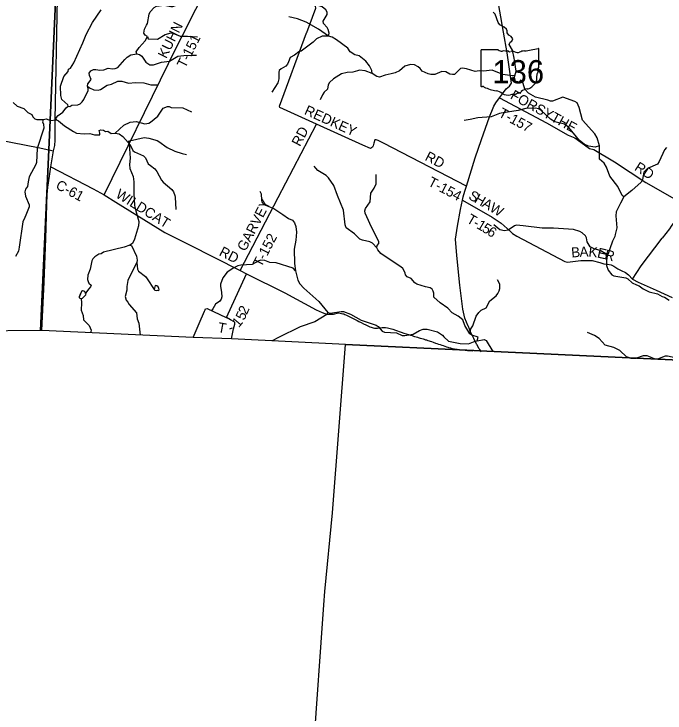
# Model space of a CAD drawing. Extents: x 1525783 to 1900577, y 218250 to 627376.
# Drawn here: x 1625264 to 1644767, y 362753 to 383684 of the extents above; entities that cross this region are included whole.
import ezdxf

# ---------------------------------------------------------------- set-up
doc = ezdxf.new("R2010")
doc.units = 0
for name, color, linetype in [('GM_X_Adjacent_County', 7, 'Continuous'), ('GM_X_County', 7, 'Continuous'), ('GM_X_County_Road', 7, 'Continuous'), ('GM_X_County_Road_Text', 7, 'Continuous'), ('GM_X_Minor_Lake', 7, 'Continuous'), ('GM_X_Minor_River', 7, 'Continuous'), ('GM_X_State_Location', 7, 'Continuous'), ('GM_X_State_Route', 7, 'Continuous'), ('GM_X_State_Shield', 7, 'Continuous'), ('GM_X_Township', 7, 'Continuous'), ('GM_X_Township_Road', 7, 'Continuous'), ('GM_X_Township_Road_Text', 7, 'Continuous'), ('GM_X_Township_ROW', 7, 'Continuous'), ('GM_X_US_Route', 7, 'Continuous')]:
    doc.layers.add(name, color=color, linetype=linetype)

msp = doc.modelspace()

# ---------------------------------------------------------------- linework, layer by layer
at = {"layer": 'GM_X_Adjacent_County'}
for points in [[(1634234, 361625), (1634548, 365997), (1634580, 366395), (1634807, 368748), (1635198, 373791), (1631776, 373952), (1630628, 373995), (1626099, 374208), (1626060, 374210), (1620148, 374148), (1613626, 374093), (1613116, 374096), (1606320, 374160)], [(1634234, 361625), (1634548, 365997), (1634580, 366395), (1634807, 368748), (1635198, 373791), (1639040, 373611), (1639218, 373602), (1647962, 373191)]]:
    msp.add_lwpolyline(points, dxfattribs=at)
at = {"layer": 'GM_X_County'}
msp.add_lwpolyline([(1647962, 373191), (1639218, 373602), (1639040, 373611), (1635198, 373791), (1631776, 373952), (1630628, 373995), (1626099, 374208), (1626060, 374210), (1620148, 374148), (1613626, 374093), (1613116, 374096), (1606320, 374160)], dxfattribs=at)
at = {"layer": 'GM_X_County_Road'}
for points in [[(1617613, 381181), (1618315, 380977), (1620831, 380241), (1621420, 380041), (1622082, 379732), (1622975, 379355), (1623023, 379332), (1623069, 379325), (1623113, 379340), (1623131, 379663), (1623129, 379761), (1623142, 379813), (1623155, 379851), (1623211, 379860), (1623949, 379621), (1624438, 379635), (1624522, 379744), (1624575, 379855), (1624634, 379916), (1624798, 379913), (1625985, 379689), (1626304, 379620), (1626453, 379588)], [(1626373, 379112), (1627634, 378447), (1627962, 378270), (1628319, 378051), (1629159, 377527), (1629779, 377138), (1630498, 376777), (1632043, 376003), (1632225, 375899), (1633377, 375335), (1634321, 374827), (1634498, 374747), (1634576, 374716), (1634632, 374696), (1634686, 374693), (1634832, 374696), (1634985, 374732), (1635076, 374718), (1635114, 374710), (1635143, 374701), (1635178, 374687), (1635230, 374664), (1635305, 374629), (1635368, 374597), (1635428, 374568), (1635487, 374537), (1635548, 374505), (1635598, 374480), (1635664, 374445), (1635735, 374408), (1635801, 374375), (1635867, 374343), (1635927, 374318), (1635967, 374303), (1635995, 374295), (1636026, 374287), (1636064, 374279), (1636107, 374275), (1636151, 374277), (1636222, 374285), (1636289, 374296), (1636351, 374299), (1636396, 374298), (1636455, 374288), (1636531, 374266), (1636611, 374242), (1636688, 374214), (1636748, 374194), (1636800, 374176), (1636866, 374153), (1636939, 374130), (1637015, 374107), (1637079, 374087), (1637143, 374067), (1637190, 374053), (1637229, 374040), (1637267, 374029), (1637313, 374017), (1637349, 374006), (1637372, 374000), (1637400, 373991), (1637430, 373981), (1637479, 373967), (1637518, 373955), (1637556, 373943), (1637591, 373931), (1637592, 373931), (1637601, 373928), (1637611, 373925), (1637617, 373923), (1637657, 373911), (1637697, 373898), (1637735, 373887), (1637775, 373874), (1637821, 373858), (1637895, 373831), (1637933, 373818), (1637984, 373802), (1638027, 373788), (1638077, 373770), (1638122, 373755), (1638172, 373737), (1638222, 373721), (1638257, 373709), (1638281, 373701), (1638341, 373683), (1638394, 373668), (1638458, 373654), (1638529, 373646), (1638558, 373642), (1638591, 373639), (1638656, 373632), (1638708, 373627), (1638851, 373611), (1638877, 373608), (1639005, 373594)]]:
    msp.add_lwpolyline(points, dxfattribs=at)
at = {"layer": 'GM_X_Minor_Lake'}
for points in [[(1629464, 375438), (1629481, 375417), (1629527, 375408), (1629559, 375410), (1629593, 375409), (1629614, 375423), (1629608, 375463), (1629585, 375512), (1629542, 375540), (1629498, 375553)], [(1629498, 375553), (1629464, 375438)], [(1627411, 375325), (1627382, 375362), (1627354, 375388), (1627321, 375395), (1627290, 375371), (1627267, 375322), (1627242, 375278), (1627234, 375256), (1627220, 375228), (1627213, 375210), (1627221, 375190), (1627241, 375174), (1627279, 375161), (1627313, 375177), (1627349, 375204), (1627370, 375224)], [(1627370, 375224), (1627421, 375275), (1627422, 375290), (1627411, 375325)]]:
    msp.add_lwpolyline(points, dxfattribs=at)
at = {"layer": 'GM_X_Minor_River'}
for points in [[(1628941, 382494), (1628921, 382546), (1629010, 382677), (1629193, 382878), (1629266, 383013), (1629194, 383054), (1629155, 383105), (1629173, 383227), (1629239, 383344), (1629266, 383396), (1629315, 383675), (1629346, 383751), (1629461, 383877), (1629533, 383916), (1629760, 383946), (1629964, 383903), (1630020, 383912), (1630135, 383952), (1630380, 384002), (1630450, 384039), (1630526, 384104), (1630844, 384467), (1631024, 384684)], [(1634686, 383020), (1634702, 383114), (1634679, 383220), (1634650, 383277), (1634534, 383397), (1634525, 383467), (1634643, 383667), (1634648, 383737), (1634609, 383812), (1634495, 383894), (1634248, 383978), (1634089, 384069), (1633965, 384165), (1633779, 384406), (1633594, 384534), (1633519, 384573), (1633253, 384683)], [(1626890, 380920), (1626882, 380962), (1626699, 381127), (1626665, 381238), (1626660, 381522), (1626759, 381807), (1626883, 381965), (1626901, 382033), (1626955, 382062), (1627062, 382217), (1627324, 382821), (1627431, 383068), (1627613, 383425), (1627872, 383811)], [(1643531, 378209), (1643479, 378250), (1643356, 378517), (1643109, 378827), (1643015, 379101), (1642941, 379220), (1642805, 379339), (1642800, 379739), (1642736, 379977), (1642662, 380100), (1642296, 380509), (1642193, 380883), (1642139, 381022), (1642069, 381061), (1641701, 381192), (1641395, 381077), (1641331, 381078), (1641253, 381101), (1640882, 381197), (1640680, 381317), (1640570, 381435), (1640519, 381604), (1640494, 381668), (1640430, 381703), (1640413, 381635), (1640359, 381632), (1640289, 381658), (1640259, 381770), (1640264, 381836), (1640309, 381972), (1640256, 382303), (1640245, 382365), (1640193, 382602), (1640094, 382772), (1640123, 382840), (1640176, 382869), (1640207, 382937), (1640162, 383007), (1640091, 383053), (1640034, 383118), (1640033, 383182), (1640016, 383234), (1639951, 383291), (1639818, 383358), (1639765, 383428), (1639677, 383674), (1639622, 383737)], [(1634686, 383020), (1634385, 383233), (1634012, 383435), (1633758, 383534), (1633497, 383600)], [(1629266, 383013), (1629282, 382935), (1629561, 382928), (1629793, 383065), (1629968, 383118), (1630026, 383111), (1630241, 383017), (1630463, 383019), (1630757, 382999)], [(1635997, 381899), (1635988, 381987), (1635912, 382128), (1635803, 382276), (1635605, 382426), (1635473, 382458), (1635339, 382552), (1635267, 382656), (1634923, 382912), (1634800, 382990), (1634686, 383020), (1634498, 383015), (1634330, 382939), (1634226, 382839), (1633867, 382567), (1633797, 382554), (1633669, 382448), (1633542, 382382), (1633486, 382247), (1633456, 382177), (1633411, 382122), (1633270, 382044), (1633207, 381989), (1633194, 381937), (1633195, 381743), (1633167, 381619), (1632984, 381342)], [(1626536, 380511), (1626525, 380575), (1626585, 380641), (1626727, 380746), (1626823, 380877), (1626890, 380920), (1626940, 380917), (1626996, 380952), (1627173, 380961), (1627245, 380994), (1627304, 381055), (1627356, 381122), (1627486, 381391), (1627485, 381457), (1627463, 381527), (1627480, 381597), (1627572, 381718), (1627526, 381843), (1627521, 381911), (1627566, 381982), (1627647, 382023), (1627719, 382024), (1627833, 382004), (1627951, 382016), (1628082, 382066), (1628218, 382041), (1628298, 382048), (1628375, 382079), (1628589, 382322), (1628652, 382387), (1628766, 382457), (1628941, 382494), (1629022, 382471), (1629090, 382423), (1629213, 382241), (1629331, 382163), (1629448, 382163), (1629504, 382182), (1629683, 382237), (1629920, 382273), (1630175, 382425), (1630351, 382439), (1630588, 382455), (1630730, 382446)], [(1640264, 381836), (1640184, 381830), (1639913, 381876), (1639585, 382004), (1639328, 381974), (1639202, 381986), (1639077, 381962), (1638824, 382046), (1638702, 382060), (1638636, 382049), (1638457, 381872), (1638401, 381867), (1638325, 381878), (1638202, 381956), (1638078, 381966), (1637874, 381872), (1637752, 381874), (1637676, 381891), (1637496, 381970), (1637431, 382049), (1637376, 382102), (1637267, 382162), (1637143, 382174), (1636976, 382123), (1636813, 381977), (1636682, 381923), (1636559, 381895), (1636380, 381854), (1636209, 381789), (1636135, 381812), (1635997, 381899), (1635788, 381978), (1635616, 381997), (1635556, 381986), (1635417, 381946), (1635242, 381933), (1635077, 381896), (1634837, 381744), (1634715, 381637), (1634671, 381562), (1634659, 381434), (1634555, 381338), (1634504, 381264), (1634435, 381111)], [(1627463, 381527), (1627528, 381472), (1627661, 381410), (1627787, 381402), (1627855, 381427), (1628058, 381555), (1628182, 381581), (1628380, 381668), (1628496, 381674), (1628693, 381609), (1628900, 381628), (1629150, 381619), (1629365, 381564), (1629556, 381567)], [(1625244, 381037), (1625358, 380927), (1625559, 380850), (1625675, 380736), (1625796, 380672), (1625829, 380605), (1625890, 380542), (1625948, 380523), (1626134, 380528), (1626186, 380531), (1626238, 380540), (1626344, 380496), (1626536, 380511), (1626594, 380486), (1626774, 380339), (1627049, 380166), (1627134, 380115), (1627368, 380095), (1627539, 380106), (1627676, 380070)], [(1628292, 380120), (1628558, 380351), (1628740, 380445), (1628924, 380462), (1629181, 380399), (1629302, 380415), (1629354, 380440), (1629572, 380629), (1629738, 380865), (1629863, 380915), (1629915, 380910), (1629974, 380881), (1630323, 380869), (1630579, 380751)], [(1642800, 379739), (1642671, 379698), (1642479, 379729), (1642342, 379781), (1642202, 379894), (1641884, 380289), (1641752, 380388), (1641468, 380454), (1641340, 380537), (1641046, 380802), (1640972, 380841), (1640883, 380863), (1640600, 380857), (1640369, 380795), (1639863, 380711), (1639807, 380700), (1639559, 380604), (1639156, 380573), (1638925, 380527), (1638748, 380493)], [(1626134, 380528), (1626119, 380458), (1626148, 380383), (1626156, 380269), (1625957, 379658), (1625938, 379241), (1625917, 379174), (1625723, 378808), (1625694, 378658), (1625668, 378517), (1625614, 378441), (1625585, 378360), (1625609, 378233), (1625716, 377971), (1625715, 377913), (1625615, 377658), (1625586, 377593), (1625532, 377465), (1625423, 376706), (1625398, 376584), (1625306, 376418)], [(1627676, 380070), (1627834, 380069), (1627837, 380119), (1627814, 380190), (1627871, 380213), (1627945, 380201), (1628008, 380170), (1628074, 380179), (1628179, 380101), (1628292, 380120), (1628415, 380091), (1628526, 380014), (1628685, 379839), (1628717, 379788), (1628746, 379371), (1628722, 379177), (1628730, 379057), (1628788, 378934), (1628836, 378817), (1628856, 378662), (1628851, 378294), (1628876, 377961), (1628889, 377897), (1629006, 377472), (1628995, 377340), (1628872, 376939), (1628816, 376816), (1628739, 376757), (1628568, 376700), (1627945, 376550), (1627880, 376501), (1627810, 376488), (1627684, 376410), (1627627, 376351), (1627600, 376290), (1627544, 376040), (1627477, 375863), (1627468, 375731), (1627483, 375677), (1627507, 375624), (1627572, 375565), (1627557, 375511), (1627504, 375454), (1627411, 375325)], [(1628685, 379839), (1628728, 379890), (1629166, 379987), (1629300, 379969), (1629549, 379892), (1629605, 379869), (1629856, 379683), (1630081, 379579), (1630302, 379505), (1630431, 379479)], [(1628717, 379788), (1628733, 379786), (1628821, 379600), (1628873, 379557), (1629143, 379441), (1629208, 379373), (1629285, 379192), (1629350, 379143), (1629481, 379046), (1629544, 378967), (1629683, 378707), (1629736, 378646), (1629991, 378431), (1630044, 378360), (1630086, 378251), (1630093, 378195), (1630117, 377834)], [(1644811, 379686), (1644750, 379613), (1644596, 379265), (1644542, 379182), (1644244, 379059), (1644128, 378948), (1644088, 378723), (1644047, 378645), (1643776, 378399), (1643531, 378209), (1643433, 378015), (1643305, 377762), (1643291, 377642), (1643323, 377285), (1643277, 377076), (1643262, 377024), (1643190, 376885), (1643023, 376395), (1643010, 376283), (1643015, 376151), (1643063, 376014), (1643169, 375876), (1643236, 375843), (1643588, 375785), (1643657, 375758), (1643787, 375629), (1643909, 375575), (1643990, 375540), (1644115, 375450), (1644294, 375368), (1644545, 375300), (1644685, 375222), (1644753, 375201), (1644890, 375114)], [(1639135, 373902), (1639168, 374003), (1638983, 374070), (1638922, 374111), (1638768, 374356), (1638705, 374528), (1638568, 374632), (1638392, 374733), (1638256, 374873), (1638027, 375034), (1637837, 375207), (1637837, 375321), (1637820, 375389), (1637787, 375442), (1637730, 375483), (1637590, 375509), (1637333, 375594), (1637272, 375629), (1637158, 375763), (1637039, 375815), (1636996, 375870), (1636983, 375928), (1636954, 375993), (1636917, 376061), (1636856, 376114), (1636323, 376458), (1636252, 376515), (1636167, 376617), (1636136, 376679), (1636003, 376824), (1635929, 376857), (1635704, 376907), (1635626, 376944), (1635461, 377099), (1635216, 377283), (1635181, 377368), (1635132, 377807), (1634954, 378253), (1634841, 378547), (1634688, 378780), (1634615, 378845), (1634368, 379002), (1634305, 379067), (1634260, 379132)], [(1636136, 376679), (1636148, 376751), (1636197, 376814), (1636192, 376876), (1635973, 377299), (1635832, 377609), (1635784, 377718), (1635777, 377789), (1635794, 377864), (1635937, 378058), (1635954, 378322), (1636055, 378469), (1636113, 378600), (1636117, 378873)], [(1632631, 378375), (1632668, 378299), (1632683, 378110), (1632701, 378040), (1632753, 377981), (1633053, 377856), (1633322, 377683), (1633484, 377564), (1633607, 377506), (1633670, 377435), (1633706, 377322), (1633732, 377151), (1633711, 376907), (1633659, 376644), (1633666, 376217), (1633694, 375998), (1633721, 375912), (1633771, 375717), (1633830, 375606), (1633945, 375476), (1634399, 375071), (1634666, 374749), (1634736, 374725), (1635061, 374780), (1635133, 374773), (1635344, 374691), (1635669, 374518), (1636117, 374370), (1636173, 374331), (1636294, 374189), (1636366, 374156), (1636722, 374132), (1636897, 374059), (1636977, 374053), (1637220, 374099), (1637410, 374210), (1637523, 374243), (1637637, 374251), (1637952, 374163), (1638096, 374063), (1638139, 374012), (1638280, 373892), (1638627, 373820), (1638877, 373812), (1639078, 373884), (1639135, 373902), (1639352, 373938), (1639413, 373911), (1639613, 373573)], [(1643023, 376395), (1642991, 376502), (1642821, 376605), (1642645, 376650), (1642526, 376716), (1642439, 376857), (1642413, 376984), (1642382, 377039), (1642287, 377132), (1642218, 377175), (1642022, 377227), (1641425, 377275), (1641088, 377266), (1640517, 377338), (1640319, 377359), (1640262, 377338), (1640072, 377209), (1639959, 377187), (1639820, 377217), (1639640, 377372)], [(1628739, 376757), (1628785, 376751), (1628938, 376436), (1628958, 376315), (1628941, 376245), (1628792, 375955), (1628671, 375701), (1628642, 375519), (1628644, 375413), (1628599, 375228), (1628629, 375111), (1628676, 375054), (1628713, 374989), (1628937, 374733), (1628958, 374551), (1629008, 374428), (1629049, 374070)], [(1628941, 376245), (1628969, 376045), (1628992, 375988), (1629202, 375828), (1629255, 375753), (1629464, 375438)], [(1633694, 375998), (1633629, 376074), (1633115, 376230), (1632925, 376246), (1632776, 376298), (1632660, 376316), (1632602, 376297), (1632402, 376178), (1632055, 376158), (1631970, 376141), (1631847, 376083), (1631655, 375958), (1631518, 375788), (1631451, 375595), (1631446, 375533), (1631484, 375344), (1631494, 375212), (1631473, 375142), (1631430, 375085), (1631298, 374991), (1631226, 374854), (1631171, 374784)], [(1638922, 374111), (1638953, 374259), (1639012, 374344), (1639109, 374633), (1639193, 374750), (1639262, 374813), (1639404, 374881), (1639515, 375095), (1639708, 375244), (1639761, 375319), (1639801, 375399), (1639818, 375461), (1639818, 375579), (1639793, 375655), (1639748, 375724)], [(1627279, 375161), (1627290, 375039), (1627273, 374815), (1627334, 374658), (1627350, 374529), (1627513, 374352), (1627573, 374213), (1627555, 374140)], [(1634666, 374749), (1634631, 374689), (1634275, 374465), (1633834, 374314), (1633191, 373992), (1633002, 373896)], [(1645234, 373308), (1645171, 373373), (1644837, 373441), (1644769, 373442), (1644542, 373351), (1644467, 373345), (1644285, 373432), (1644229, 373449), (1644107, 373447), (1643881, 373372), (1643749, 373367), (1643616, 373417), (1643409, 373605), (1643329, 373650), (1643236, 373698), (1642975, 373772), (1642796, 373969), (1642653, 374054), (1642449, 374147)]]:
    msp.add_lwpolyline(points, dxfattribs=at)
at = {"layer": 'GM_X_State_Route'}
for points in [[(1638875, 374323), (1638871, 374332), (1638771, 374579), (1638713, 374841), (1638615, 375568), (1638535, 376455), (1638495, 376941), (1638552, 377333), (1638640, 377833), (1638697, 378107), (1638723, 378212), (1638769, 378380), (1638820, 378528), (1639083, 379381), (1639266, 379924), (1639507, 380600), (1639614, 380870), (1639641, 380926), (1639703, 381027), (1639813, 381178), (1639926, 381333), (1640012, 381447), (1640108, 381526), (1640151, 381582), (1640165, 381615), (1640034, 382519), (1639926, 383141), (1639742, 384242)], [(1639204, 373654), (1639163, 373723), (1639135, 373777), (1639130, 373786), (1639082, 373881), (1639039, 373967), (1638997, 374051), (1638953, 374141), (1638906, 374243), (1638875, 374323)], [(1639270, 373570), (1639216, 373634), (1639204, 373654)]]:
    msp.add_lwpolyline(points, dxfattribs=at)
at = {"layer": 'GM_X_State_Shield'}
for p, q in [((1640985, 382081), (1640985, 382634)), ((1639245, 382589), (1639245, 381533)), ((1639772, 382607), (1639262, 382607)), ((1640985, 382081), (1640985, 382081))]:
    msp.add_line(p, q, dxfattribs=at)
for centre, major_axis, start_param, end_param in [((1640365, 384048), (1845, 0), 4.814394, 5.042369), ((1640966, 382636), (19.4, 0), 6.141152, 7.989035), ((1639265, 382591), (20.2, 0), 1.712693, 3.28349), ((1639893, 382730), (196, 0), 4.042523, 4.731795), ((1639958, 382014), (702, 0), 1.404758, 1.657858), ((1640117, 382597), (56.4, 0), 3.836095, 5.185415), ((1640200, 382475), (117, 0), 0.950623, 2.079405), ((1640351, 382642), (141, 0), 4.081561, 5.145723), ((1640601, 382285), (371, 0), 1.699011, 2.107814), ((1640981, 382040), (30, 0), 1.883978, 3.671073), ((1640790, 381970), (180, 0), 5.934695, 6.695948), ((1640964, 382079), (20.7, 0), 5.05454, 6.418171), ((1640469, 381779), (462, 0), 5.101752, 6.440018), ((1641054, 381850), (131, 0), 2.387724, 3.262537), ((1639265, 381530), (20.3, 0), 3.00124, 4.508301), ((1639268, 381638), (155, 0), 4.665946, 4.897461), ((1639300, 381472), (56, 0), 0.519207, 1.627899), ((1640006, 382421), (1333, 0), 4.195997, 4.488961), ((1639609, 381058), (417, 0), 0.823519, 1.323587), ((1640663, 381236), (253, 0), 1.647645, 2.488434), ((1640060, 381466), (265, 0), 4.026481, 4.996735), ((1640213, 381101), (217, 0), 1.495662, 1.94098), ((1640232, 381387), (141, 0), 4.691044, 5.507374), ((1640360, 381285), (39.7, 0), 1.147584, 2.315152), ((1640343, 381430), (149, 0), 4.937069, 5.64225)]:
    msp.add_ellipse(centre, major_axis=major_axis, ratio=0.8, start_param=start_param, end_param=end_param, dxfattribs=at)
at = {"layer": 'GM_X_Township'}
for points in [[(1626547, 384955), (1626304, 379620), (1626060, 374210), (1620148, 374148), (1613626, 374093), (1613116, 374096), (1606320, 374160)], [(1647962, 373191), (1639218, 373602), (1639040, 373611), (1635198, 373791), (1631776, 373952), (1630628, 373995), (1626099, 374208), (1626060, 374210), (1626304, 379620), (1626547, 384955)]]:
    msp.add_lwpolyline(points, dxfattribs=at)
at = {"layer": 'GM_X_Township_Road'}
for points in [[(1629926, 382269), (1629927, 382271), (1631097, 384609), (1631463, 385360), (1632385, 387361), (1632999, 390074)], [(1634032, 383125), (1634305, 383861), (1634298, 383913), (1634273, 383948), (1634300, 383984)], [(1638820, 378528), (1636336, 379820), (1636169, 379899), (1636113, 379920), (1636075, 379913), (1636045, 379811), (1636021, 379736), (1636000, 379696), (1635943, 379653), (1635715, 379758), (1634322, 380389), (1633233, 380883), (1633215, 380926), (1634031, 383123), (1634032, 383125)], [(1639813, 381178), (1641220, 380421), (1641862, 380056), (1642067, 379972), (1642502, 379658), (1642630, 379628), (1643252, 379255), (1644194, 378642), (1645399, 377949)], [(1632043, 376003), (1633182, 378192), (1634322, 380389)], [(1638697, 378107), (1639593, 377600), (1639862, 377423), (1640124, 377181), (1640197, 377115), (1640330, 377032), (1641764, 376274), (1641846, 376255), (1642248, 376299), (1642585, 376304), (1642809, 376246), (1642934, 376201), (1643040, 376193), (1643156, 376175), (1643229, 376129), (1643352, 376049), (1643451, 376003), (1643579, 375948), (1643668, 375878), (1643789, 375741), (1643960, 375650), (1644505, 375418), (1644984, 375198)], [(1645399, 377949), (1644955, 377329), (1644896, 377252), (1644681, 376969)], [(1630628, 373995), (1630815, 374416), (1630974, 374786), (1630989, 374830), (1631006, 374852), (1631048, 374861), (1631620, 374593), (1631632, 374591), (1632225, 375899)], [(1631776, 373952), (1631843, 374253), (1631876, 374399), (1631884, 374450), (1631860, 374462), (1631749, 374527), (1631632, 374591)]]:
    msp.add_lwpolyline(points, dxfattribs=at)
at = {"layer": 'GM_X_Township_ROW'}
for points in [[(1627962, 378270), (1629892, 382201), (1629926, 382269)], [(1643789, 375741), (1644051, 376140), (1644681, 376969)]]:
    msp.add_lwpolyline(points, dxfattribs=at)
at = {"layer": 'GM_X_US_Route'}
msp.add_lwpolyline([(1626099, 374208), (1626164, 375656), (1626214, 376949), (1626248, 377977), (1626259, 378278), (1626283, 378495), (1626333, 378830), (1626373, 379112), (1626453, 379588), (1626487, 379744), (1626498, 379906), (1626496, 380508), (1626573, 384168), (1626596, 384866), (1626614, 385250), (1626694, 386483), (1626716, 386972), (1626737, 387835), (1626755, 388652), (1626761, 389086), (1626765, 389240), (1626769, 389345)], dxfattribs=at)

# ---------------------------------------------------------------- texts
at = {"layer": 'GM_X_County_Road_Text'}
for s, rotation, p in [('C-61', 331.9065, (1626491, 378469)), ('WILDCAT', 328.168, (1628286, 378210)), ('RD', 333.2117, (1631387, 376469))]:
    msp.add_text(s, height=300, rotation=rotation, dxfattribs=at).set_placement(p)
at = {"layer": 'GM_X_State_Location'}
msp.add_text('136', height=1, rotation=0, dxfattribs=at).set_placement((1639742, 381918))
for s in ['s', 'r']:
    msp.add_text(s, height=1, dxfattribs=at).set_placement((1640095, 381991))
at = {"layer": 'GM_X_State_Shield'}
msp.add_text('136', height=696.1, dxfattribs=at).set_placement((1639593, 381607))
at = {"layer": 'GM_X_Township_Road_Text'}
for s, rotation, p in [('KUHN', 63.4349, (1629825, 382330)), ('T-151', 63.5602, (1630397, 382041)), ('FORSYTHE', 331.2413, (1640107, 381162)), ('REDKEY', 335.5562, (1633938, 380692)), ('T-157', 331.5468, (1639754, 380627)), ('RD', 62.333, (1633830, 379696)), ('RD', 332.333, (1637551, 379320)), ('RD', 327.2653, (1643828, 379024)), ('T-154', 332.5553, (1637641, 378559)), ('S', 330.1213, (1638855, 378160)), ('H', 330.1187, (1639031, 378059)), ('GARVEY', 62.4727, (1632197, 376555)), ('A', 330.0943, (1639260, 377928)), ('W', 328.8261, (1639487, 377797)), ('T', 329.9341, (1638800, 377457)), ('-', 329.7846, (1638994, 377345)), ('1', 329.312, (1639100, 377283)), ('5', 328.4508, (1639257, 377190)), ('6', 327.0229, (1639413, 377094)), ('T-152', 62.5555, (1632672, 376080)), ('B', 5.202, (1641970, 376389)), ('A', 2.343, (1642211, 376411)), ('K', 354.0186, (1642464, 376422)), ('E', 347.2964, (1642717, 376396)), ('R', 345.8648, (1642934, 376347)), ('2', 65.5919, (1632237, 374661)), ('5', 65.5919, (1632161, 374492)), ('1', 50.4052, (1631997, 374277)), ('T', 349.6584, (1631350, 374161)), ('-', 20.0318, (1631741, 374136))]:
    msp.add_text(s, height=300, rotation=rotation, dxfattribs=at).set_placement(p)

doc.saveas('drawing.dxf')
